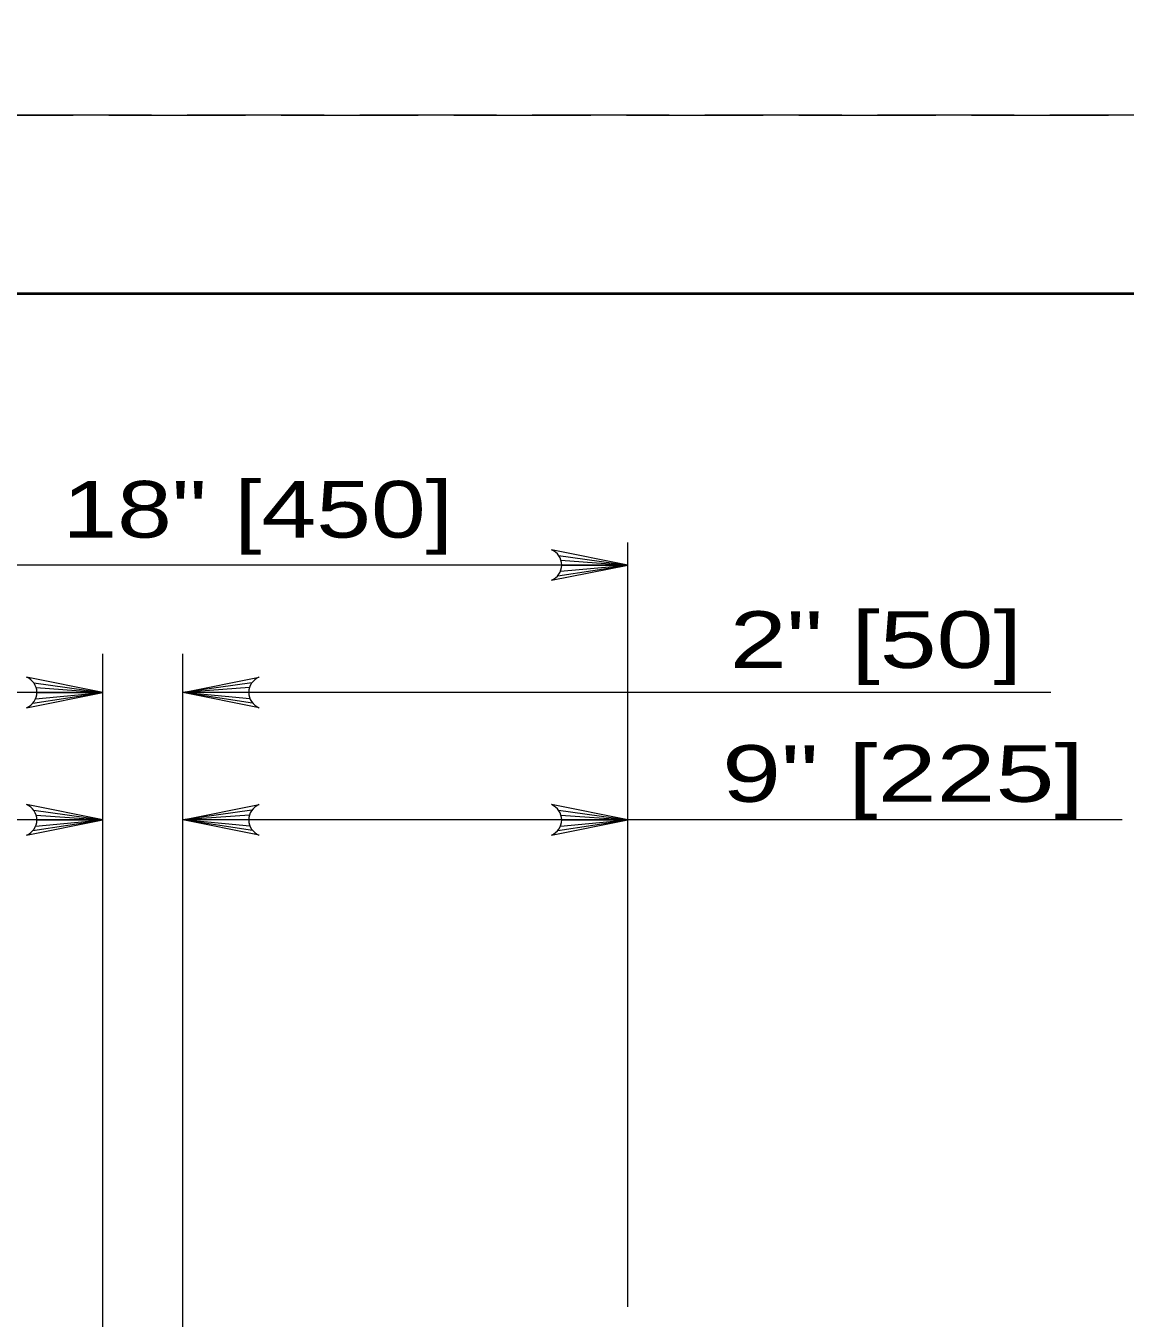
# Model space of a CAD drawing. Extents: x -1431.2 to -1397.2, y -1045.1 to -1001.1.
# Drawn here: x -1422.282 to -1419.199, y -1026.453 to -1022.83 of the extents above; entities that cross this region are included whole.
import ezdxf
from ezdxf.enums import TextEntityAlignment as Align

# ---------------------------------------------------------------- set-up
doc = ezdxf.new("R2010")
doc.units = 0
doc.header["$LTSCALE"] = 0.064
doc.linetypes.add('LONG_DASHED', pattern=[7.5, 6, -1.5])
doc.layers.add('1', color=7, linetype='Continuous', lineweight=13)

msp = doc.modelspace()

# ---------------------------------------------------------------- linework, layer by layer
at = {"layer": '1', "lineweight": 25}
msp.add_line((-1429.24575, -1023.57983), (-1397.74575, -1023.57983), dxfattribs=at)
at = {"layer": '1'}
for p, q in [((-1420.594, -1026.42058), (-1420.594, -1024.27858)), ((-1420.594, -1024.34142), (-1422.764, -1024.34142)), ((-1420.79, -1024.37133), (-1420.594, -1024.34142)), ((-1420.78775, -1024.31433), (-1420.594, -1024.34142)), ((-1420.78258, -1024.35883), (-1420.594, -1024.34142)), ((-1420.78117, -1024.32775), (-1420.594, -1024.34142)), ((-1420.77917, -1024.34142), (-1420.594, -1024.34142)), ((-1422.06608, -1027.90533), (-1422.06608, -1024.5905)), ((-1421.842, -1026.48467), (-1421.842, -1024.5905)), ((-1422.06608, -1024.69867), (-1422.58025, -1024.69867)), ((-1422.26208, -1024.72858), (-1422.06608, -1024.69867)), ((-1422.25975, -1024.6715), (-1422.06608, -1024.69867)), ((-1422.25467, -1024.716), (-1422.06608, -1024.69867)), ((-1422.25325, -1024.68492), (-1422.06608, -1024.69867)), ((-1422.25125, -1024.69867), (-1422.06608, -1024.69867)), ((-1421.64833, -1024.6715), (-1421.842, -1024.69867)), ((-1421.65492, -1024.68492), (-1421.842, -1024.69867)), ((-1421.65692, -1024.69867), (-1421.842, -1024.69867)), ((-1421.6535, -1024.716), (-1421.842, -1024.69867)), ((-1421.64608, -1024.72858), (-1421.842, -1024.69867)), ((-1419.40767, -1024.69867), (-1421.842, -1024.69867)), ((-1422.25975, -1025.02875), (-1422.06608, -1025.05583)), ((-1421.64833, -1025.02875), (-1421.842, -1025.05583)), ((-1420.78775, -1025.02875), (-1420.594, -1025.05583)), ((-1422.06608, -1025.05583), (-1424.0665, -1025.05583)), ((-1422.26208, -1025.08583), (-1422.06608, -1025.05583)), ((-1422.25467, -1025.07325), (-1422.06608, -1025.05583)), ((-1422.25325, -1025.04217), (-1422.06608, -1025.05583)), ((-1422.25125, -1025.05583), (-1422.06608, -1025.05583)), ((-1421.65492, -1025.04217), (-1421.842, -1025.05583)), ((-1421.65692, -1025.05583), (-1421.842, -1025.05583)), ((-1421.6535, -1025.07325), (-1421.842, -1025.05583)), ((-1421.64608, -1025.08583), (-1421.842, -1025.05583)), ((-1419.20758, -1025.05583), (-1421.842, -1025.05583)), ((-1419.20758, -1025.05583), (-1421.842, -1025.05583)), ((-1420.79, -1025.08583), (-1420.594, -1025.05583)), ((-1420.78258, -1025.07325), (-1420.594, -1025.05583)), ((-1420.78117, -1025.04217), (-1420.594, -1025.05583)), ((-1420.77917, -1025.05583), (-1420.594, -1025.05583))]:
    msp.add_line(p, q, dxfattribs=at)
at = {"layer": '1', "linetype": 'LONG_DASHED'}
for points in [[(-1431.24575, -1023.07983), (-1397.24575, -1023.07983), (-1397.24575, -1001.07983), (-1431.24575, -1001.07983)], [(-1431.24575, -1045.07983), (-1397.24575, -1045.07983), (-1397.24575, -1023.07983), (-1431.24575, -1023.07983)]]:
    msp.add_lwpolyline(points, close=True, dxfattribs=at)
at = {"layer": '1', "lineweight": 40}
msp.add_lwpolyline([(-1429.24575, -1023.57983), (-1397.74575, -1023.57983), (-1397.74575, -1044.57983), (-1429.24575, -1044.57983)], close=True, dxfattribs=at)
at = {"layer": '1'}
for points in [[(-1420.808, -1024.38417), (-1420.594, -1024.34142), (-1420.808, -1024.29858)], [(-1422.28, -1024.74142), (-1422.06608, -1024.69867), (-1422.28, -1024.65583)], [(-1421.62808, -1024.74142), (-1421.842, -1024.69867), (-1421.62808, -1024.65583)], [(-1422.28, -1025.09867), (-1422.06608, -1025.05583), (-1422.28, -1025.01308)], [(-1421.62808, -1025.09867), (-1421.842, -1025.05583), (-1421.62808, -1025.01308)], [(-1420.808, -1025.09867), (-1420.594, -1025.05583), (-1420.808, -1025.01308)]]:
    msp.add_lwpolyline(points, dxfattribs=at)
for centre, start, end in [((-1420.82527, -1024.34135), 292.08605, 67.91218), ((-1422.29731, -1024.69858), 292.08605, 67.91218), ((-1421.6108, -1024.69858), 112.08782, 247.91395), ((-1422.29731, -1025.0558), 292.08605, 67.91218), ((-1421.6108, -1025.0558), 112.08782, 247.91395), ((-1420.82527, -1025.0558), 292.08605, 67.91218)]:
    msp.add_arc(centre, 0.04618, start, end, dxfattribs=at)

# ---------------------------------------------------------------- texts
for s, width, p in [('18" [450]', 1.3, (-1421.63167, -1024.2645)), ('2" [50]', 1.35, (-1419.89812, -1024.62983)), ('9" [225]', 1.4, (-1419.82187, -1025.00517))]:
    msp.add_text(s, height=0.1588, dxfattribs=dict(at, width=width)).set_placement(p, align=Align.CENTER)

doc.saveas('drawing.dxf')
